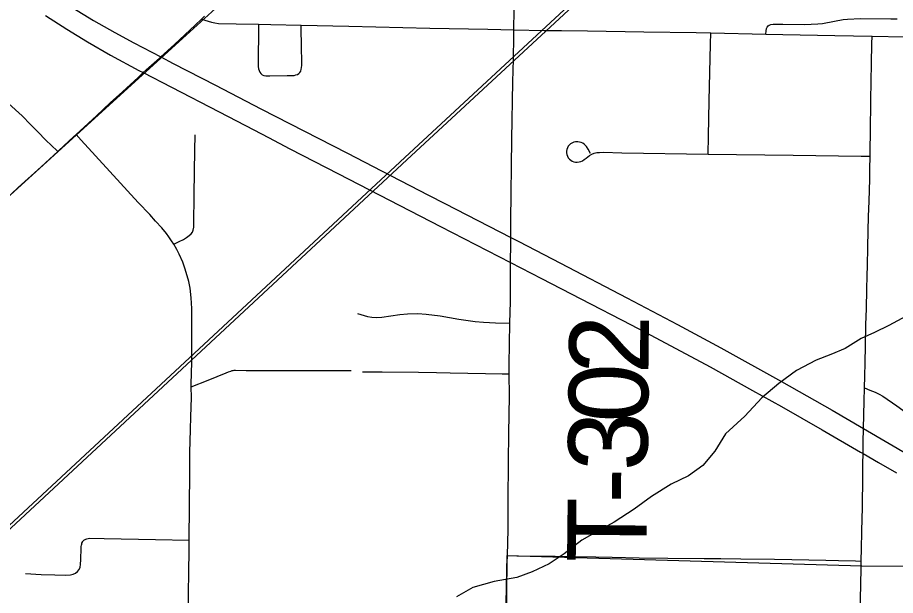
# Model space of a CAD drawing. Extents: x 0 to 34, y 0 to 22.
# Drawn here: x 4.642 to 5.271, y 18.383 to 18.797 of the extents above; entities that cross this region are included whole.
import ezdxf

# ---------------------------------------------------------------- set-up
doc = ezdxf.new("R2010")
doc.units = 0
for name, color, linetype in [('GM_X_Corporation', 7, 'Continuous'), ('GM_X_Interstate_Route', 7, 'Continuous'), ('GM_X_Minor_River', 7, 'Continuous'), ('GM_X_Rail_Line', 7, 'Continuous'), ('GM_X_State_Route', 7, 'Continuous'), ('GM_X_Township_Road', 7, 'Continuous'), ('GM_X_Township_Road_Text', 7, 'Continuous')]:
    doc.layers.add(name, color=color, linetype=linetype)

msp = doc.modelspace()

# ---------------------------------------------------------------- linework, layer by layer
at = {"layer": 'GM_X_Corporation'}
msp.add_lwpolyline([(5.24691, 18.40433), (5.49728, 18.40367), (5.48857, 17.88606), (4.98239, 17.89994), (4.99301, 18.41185)], close=True, dxfattribs=at)
at = {"layer": 'GM_X_Interstate_Route'}
for points in [[(4.68203, 18.80395), (4.69689, 18.79482), (4.71201, 18.78616), (4.7257, 18.77876), (4.74502, 18.7687), (4.75383, 18.7641), (4.78422, 18.74845), (4.81676, 18.73152), (4.87871, 18.69973), (4.90303, 18.6872), (4.93669, 18.66974), (4.94829, 18.66375), (4.99562, 18.63953), (5.00142, 18.63656), (5.03123, 18.62113), (5.0786, 18.59634), (5.1149, 18.57723), (5.14607, 18.56041), (5.18958, 18.53633), (5.22582, 18.51584), (5.24813, 18.50277), (5.28214, 18.48285)], [(4.66256, 18.79845), (4.67765, 18.78864), (4.69245, 18.77953), (4.70911, 18.76989), (4.72937, 18.75905), (4.73237, 18.7575), (4.75258, 18.74711), (4.78682, 18.72939), (4.81163, 18.71644), (4.82212, 18.71101), (4.83749, 18.70287), (4.87236, 18.68502), (4.94533, 18.64745), (4.99544, 18.62159), (5.0177, 18.61008), (5.04586, 18.59551), (5.08173, 18.57689), (5.09939, 18.56771), (5.13831, 18.54686), (5.16881, 18.53005), (5.18939, 18.51843), (5.21853, 18.50174), (5.24599, 18.48589), (5.24786, 18.4848), (5.25889, 18.47839), (5.27179, 18.47089)]]:
    msp.add_lwpolyline(points, dxfattribs=at)
at = {"layer": 'GM_X_Minor_River'}
msp.add_lwpolyline([(5.28537, 18.58674), (5.26635, 18.57635), (5.25608, 18.57155), (5.24658, 18.56711), (5.23516, 18.56004), (5.2249, 18.55562), (5.21427, 18.55158), (5.2002, 18.54416), (5.18761, 18.53483), (5.17539, 18.52474), (5.16313, 18.51161), (5.14937, 18.49887), (5.14165, 18.48644), (5.13321, 18.4763), (5.12291, 18.46884), (5.11037, 18.46293), (5.09628, 18.45399), (5.08407, 18.44504), (5.06959, 18.43573), (5.05742, 18.42905), (5.04638, 18.42274), (5.03379, 18.41302), (5.02312, 18.40595), (5.01096, 18.40003), (4.99995, 18.39599), (4.98367, 18.39316), (4.9685, 18.38879), (4.9567, 18.38211)], dxfattribs=at)
at = {"layer": 'GM_X_Rail_Line'}
for points in [[(4.0369, 17.87629), (4.0405, 17.87963), (4.10582, 17.94022), (4.26502, 18.087), (4.55609, 18.35576), (4.76707, 18.55171), (4.9213, 18.69505), (5.34845, 19.09084), (6.00629, 19.70228), (6.04051, 19.73365)], [(4.26344, 18.0887), (4.5545, 18.35746), (4.76549, 18.55341), (4.91971, 18.69674), (5.34686, 19.09254), (6.00471, 19.70399), (6.03893, 19.73535)], [(2.20624, 17.40963), (2.27317, 17.34884), (2.53129, 17.30267), (2.6424, 17.31122), (3.24752, 17.60363), (3.90003, 17.91971), (3.99131, 17.98254), (4.33797, 18.26064), (4.40078, 18.3243), (4.44097, 18.38712), (4.46358, 18.43738), (4.47865, 18.49769), (4.49623, 18.5312), (4.52052, 18.56387), (4.5582, 18.59821), (4.78429, 18.80343)]]:
    msp.add_lwpolyline(points, dxfattribs=at)
at = {"layer": 'GM_X_State_Route'}
for points in [[(4.72869, 18.75407), (4.73237, 18.7575), (4.73443, 18.75942), (4.74414, 18.76789), (4.74502, 18.7687), (4.75485, 18.77762), (4.76953, 18.79143), (4.77415, 18.79589), (4.77625, 18.79791)], [(4.62785, 18.6613), (4.64279, 18.67526), (4.65939, 18.69005), (4.67134, 18.70108), (4.67209, 18.70176), (4.6828, 18.71173), (4.68437, 18.71318), (4.6989, 18.7266), (4.7087, 18.73583), (4.71766, 18.7438), (4.72869, 18.75407)]]:
    msp.add_lwpolyline(points, dxfattribs=at)
at = {"layer": 'GM_X_Township_Road'}
msp.add_line((5.13876, 18.78591), (5.1782, 18.78498), dxfattribs=at)
for points in [[(4.99779, 18.78826), (4.99803, 18.80249), (4.99802, 18.81534), (4.99858, 18.85671), (4.99892, 18.87663)], [(4.77415, 18.79589), (4.77893, 18.79436), (4.78136, 18.79359), (4.78365, 18.79307), (4.78644, 18.79277), (4.79889, 18.79248), (4.81506, 18.79212)], [(5.1782, 18.78498), (5.17839, 18.78751), (5.17879, 18.7891), (5.17923, 18.79015), (5.17984, 18.79096), (5.18068, 18.79157), (5.18183, 18.792), (5.18344, 18.79223), (5.19037, 18.7921), (5.20592, 18.792), (5.2154, 18.79235), (5.21889, 18.79274), (5.22748, 18.7944), (5.2336, 18.79546), (5.23667, 18.79589), (5.24597, 18.79628), (5.26764, 18.796), (5.27235, 18.79594)], [(4.81506, 18.79212), (4.81497, 18.78599), (4.8147, 18.76807), (4.81483, 18.76194), (4.81494, 18.76034), (4.81534, 18.75907), (4.81597, 18.7578), (4.81668, 18.75686), (4.81752, 18.75603), (4.8187, 18.75547), (4.82017, 18.75516), (4.82313, 18.75513), (4.83541, 18.75544), (4.83847, 18.75547), (4.84053, 18.75556), (4.84172, 18.75584), (4.84294, 18.75624), (4.84385, 18.75679), (4.8446, 18.75754), (4.84524, 18.75861), (4.84563, 18.75987), (4.84583, 18.76087), (4.846, 18.76292), (4.84576, 18.7782), (4.84561, 18.7874), (4.84563, 18.79149)], [(4.81506, 18.79212), (4.82375, 18.79192), (4.84563, 18.79149), (4.87969, 18.79082), (4.93756, 18.78929), (4.97913, 18.78869), (4.99779, 18.78826)], [(4.99497, 18.57814), (4.99551, 18.59354), (4.99544, 18.62159), (4.99558, 18.63517), (4.99562, 18.63953), (4.99574, 18.65156), (4.99636, 18.70988), (4.99699, 18.75101), (4.99755, 18.76722), (4.99771, 18.78336), (4.99779, 18.78826)], [(4.99779, 18.78826), (5.01953, 18.78776), (5.03195, 18.78755), (5.0506, 18.78742), (5.09099, 18.78672), (5.12829, 18.78616), (5.13876, 18.78591)], [(5.13705, 18.69919), (5.13729, 18.71203), (5.13778, 18.73734), (5.13853, 18.77795), (5.13876, 18.78591)], [(5.1782, 18.78498), (5.19044, 18.7847), (5.22774, 18.78399), (5.25435, 18.78352)], [(5.25285, 18.6976), (5.25292, 18.70231), (5.2531, 18.71482), (5.25343, 18.73778), (5.2537, 18.75118), (5.25396, 18.76392), (5.25425, 18.77815), (5.25435, 18.78352)], [(5.25435, 18.78352), (5.27744, 18.78309), (5.32094, 18.78197), (5.35549, 18.78127)], [(4.61763, 18.74443), (4.61993, 18.74405), (4.62311, 18.74339), (4.62466, 18.74285), (4.62595, 18.74234), (4.62839, 18.74096), (4.63103, 18.73933), (4.63276, 18.73801), (4.63598, 18.7354), (4.64568, 18.7266), (4.65175, 18.72042), (4.65639, 18.71571), (4.66325, 18.70873), (4.66639, 18.70577), (4.67134, 18.70108)], [(4.75433, 18.63479), (4.75269, 18.63719), (4.75085, 18.6399), (4.74911, 18.64229), (4.74564, 18.6463), (4.74129, 18.65118), (4.73706, 18.65585), (4.72892, 18.66442), (4.70861, 18.68666), (4.68799, 18.70922), (4.68437, 18.71318)], [(4.75433, 18.63479), (4.7581, 18.63663), (4.76118, 18.63813), (4.76347, 18.63956), (4.76528, 18.6409), (4.76671, 18.64217), (4.76766, 18.64335), (4.76828, 18.64477), (4.7686, 18.64683), (4.76868, 18.64927), (4.76899, 18.66966), (4.7692, 18.68679), (4.76938, 18.70164), (4.76952, 18.71286)], [(5.05271, 18.69957), (5.05111, 18.70266), (5.04973, 18.70469), (5.04845, 18.70611), (5.04718, 18.70698), (5.04609, 18.70752), (5.04486, 18.70781), (5.04351, 18.70803), (5.04205, 18.70796), (5.04082, 18.70766), (5.03944, 18.70712), (5.03831, 18.70647), (5.03755, 18.70578), (5.03682, 18.7049), (5.03621, 18.70378), (5.03577, 18.70258), (5.03559, 18.70134), (5.03563, 18.7), (5.03577, 18.69894), (5.03618, 18.69767), (5.03672, 18.69658), (5.03759, 18.69549), (5.03854, 18.69473), (5.03966, 18.69408), (5.04076, 18.69357), (5.04195, 18.69331), (5.04317, 18.6933), (5.04461, 18.69353), (5.04584, 18.6939), (5.04707, 18.6944), (5.04827, 18.69521), (5.04962, 18.69615), (5.05209, 18.69815), (5.05362, 18.69906), (5.05543, 18.69982), (5.05718, 18.70026), (5.05917, 18.70044), (5.06191, 18.70051), (5.07511, 18.7), (5.13705, 18.69919)], [(5.13705, 18.69919), (5.19783, 18.69833), (5.24651, 18.69769), (5.25285, 18.6976)], [(5.24883, 18.53189), (5.24904, 18.54009), (5.24927, 18.54981), (5.24957, 18.56182), (5.24993, 18.57687), (5.25026, 18.58872), (5.25064, 18.60227), (5.25091, 18.61224), (5.25105, 18.61923), (5.25131, 18.63248), (5.25155, 18.64415), (5.25184, 18.65443), (5.25216, 18.66554), (5.25261, 18.68126), (5.25271, 18.68833), (5.25285, 18.6976)], [(4.76685, 18.53259), (4.76709, 18.5442), (4.76713, 18.54832), (4.76719, 18.55353), (4.76727, 18.56005), (4.76728, 18.56623), (4.7673, 18.58373), (4.76727, 18.58874), (4.76684, 18.59625), (4.76599, 18.60309), (4.76506, 18.60786), (4.76258, 18.61668), (4.76073, 18.62189), (4.75813, 18.62764), (4.7565, 18.6309), (4.75433, 18.63479)], [(4.88582, 18.58507), (4.89306, 18.58303), (4.89623, 18.58246), (4.89942, 18.58228), (4.9032, 18.58248), (4.91617, 18.58426), (4.92167, 18.58478), (4.92902, 18.58498), (4.93514, 18.58458), (4.94494, 18.58334), (4.9584, 18.58101), (4.97015, 18.57936), (4.97618, 18.57877), (4.98469, 18.5783), (4.99497, 18.57814)], [(4.99455, 18.54183), (4.9945, 18.54858), (4.99497, 18.57814)], [(4.76685, 18.53259), (4.77882, 18.53736), (4.79172, 18.54261), (4.79356, 18.54333), (4.79505, 18.54387), (4.79605, 18.54419), (4.79691, 18.54437), (4.79765, 18.54442), (4.79844, 18.54446), (4.80618, 18.54433), (4.82276, 18.54431), (4.82864, 18.5443), (4.8393, 18.54429), (4.85053, 18.54427), (4.86309, 18.54426), (4.8721, 18.54424), (4.88143, 18.54424)], [(4.88938, 18.54341), (4.89061, 18.54336), (4.90358, 18.54336), (4.92951, 18.54311), (4.94234, 18.54291), (4.95221, 18.54268), (4.97759, 18.54221), (4.98934, 18.54195), (4.99455, 18.54183)], [(4.99325, 18.41176), (4.99375, 18.43033), (4.99374, 18.45041), (4.99405, 18.47917), (4.99414, 18.49906), (4.99467, 18.52616), (4.99455, 18.54183)], [(4.7654, 18.42288), (4.76568, 18.44725), (4.76575, 18.47089), (4.7659, 18.48564), (4.76637, 18.50198), (4.76659, 18.51118), (4.76692, 18.52482), (4.76685, 18.53259)], [(5.24657, 18.40786), (5.24679, 18.41712), (5.24706, 18.42856), (5.24729, 18.43884), (5.24744, 18.44525), (5.24752, 18.45274), (5.2476, 18.4617), (5.24768, 18.46935), (5.24776, 18.47742), (5.24786, 18.4848), (5.24798, 18.49296), (5.24813, 18.50277), (5.2486, 18.52233), (5.24883, 18.53189)], [(5.24883, 18.53189), (5.25269, 18.53027), (5.25656, 18.52864), (5.25948, 18.52725), (5.26192, 18.52579), (5.27196, 18.51893), (5.30126, 18.49791), (5.31788, 18.48593), (5.3333, 18.4755), (5.33545, 18.47415)], [(4.64819, 18.39886), (4.65934, 18.39828), (4.66924, 18.39786), (4.67666, 18.39771), (4.68037, 18.39799), (4.68218, 18.3984), (4.68387, 18.39918), (4.68534, 18.40032), (4.68649, 18.40176), (4.68724, 18.40345), (4.6876, 18.40527), (4.68773, 18.409), (4.68794, 18.41707), (4.68805, 18.41814), (4.68823, 18.41915), (4.68841, 18.42003), (4.68857, 18.4207), (4.68911, 18.42188), (4.6895, 18.42241), (4.68996, 18.42284), (4.69127, 18.42356), (4.69215, 18.42384), (4.69303, 18.424), (4.69388, 18.4241), (4.70445, 18.42402), (4.74122, 18.42334), (4.7654, 18.42288)], [(4.7624, 18.24722), (4.76259, 18.25417), (4.76284, 18.2749), (4.76308, 18.28617), (4.7634, 18.30164), (4.76364, 18.31134), (4.76388, 18.32919), (4.76404, 18.3389), (4.76428, 18.35223), (4.7646, 18.37065), (4.76484, 18.38414), (4.76508, 18.40035), (4.76524, 18.41483), (4.7654, 18.42288)], [(4.99184, 18.31605), (4.99187, 18.32413), (4.99212, 18.35301), (4.9927, 18.37431), (4.99285, 18.38649), (4.99312, 18.40671), (4.99325, 18.41176)], [(4.99325, 18.41176), (4.99996, 18.41166), (5.02731, 18.4113), (5.03786, 18.41098), (5.05649, 18.41076), (5.06831, 18.4106), (5.08756, 18.4102), (5.10806, 18.40997), (5.13415, 18.40974), (5.14595, 18.40974), (5.16024, 18.40953), (5.18449, 18.40929), (5.19691, 18.40895), (5.22114, 18.40852), (5.23034, 18.40828), (5.24242, 18.40797), (5.24657, 18.40786)], [(5.2446, 18.27277), (5.24467, 18.27876), (5.24489, 18.29752), (5.24554, 18.35176), (5.24579, 18.36892), (5.24596, 18.38033), (5.24645, 18.40256), (5.24657, 18.40786)]]:
    msp.add_lwpolyline(points, dxfattribs=at)

# ---------------------------------------------------------------- texts
at = {"layer": 'GM_X_Township_Road_Text'}
for s, rotation, p in [('2', 89.36296, (5.09416, 18.54149)), ('0', 89.37955, (5.09378, 18.50678)), ('3', 89.3798, (5.0934, 18.47206)), ('-', 89.37295, (5.09315, 18.44893)), ('T', 89.34133, (5.09266, 18.40648))]:
    msp.add_text(s, height=0.05682, rotation=rotation, dxfattribs=at).set_placement(p)

doc.saveas('drawing.dxf')
